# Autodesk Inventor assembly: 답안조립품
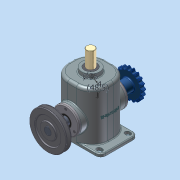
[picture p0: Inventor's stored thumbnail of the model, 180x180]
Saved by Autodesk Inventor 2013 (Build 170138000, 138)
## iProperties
Created: 2014-12
Part Number: 답안조립품
Document SubType Name: Assembly
Designer: WINDOWS7
Author: WINDOWS7
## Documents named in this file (15)
- C:\Users\WINDOWS7\Desktop\341209V1022\답안조립품.iam
- C:\Users\WINDOWS7\Desktop\341209V1022\M4x0.5.ipt
- C:\Users\WINDOWS7\Desktop\341209V1022\V-벨트풀리.ipt
- C:\Users\WINDOWS7\Desktop\341209V1022\멈춤나사 M5x0.5.ipt
- C:\Users\WINDOWS7\Desktop\341209V1022\멈춤링.ipt
- C:\Users\WINDOWS7\Desktop\341209V1022\베어링 6205.ipt
- C:\Users\WINDOWS7\Desktop\341209V1022\본체.ipt
- C:\Users\WINDOWS7\Desktop\341209V1022\부시.ipt
- C:\Users\WINDOWS7\Desktop\341209V1022\스프링-[가변].ipt
- C:\Users\WINDOWS7\Desktop\341209V1022\슬라이드.ipt
- C:\Users\WINDOWS7\Desktop\341209V1022\오일실.ipt
- C:\Users\WINDOWS7\Desktop\341209V1022\체인 스프로킷.ipt
- C:\Users\WINDOWS7\Desktop\341209V1022\커버.ipt
- C:\Users\WINDOWS7\Desktop\341209V1022\키 8x8.ipt
- C:\Users\WINDOWS7\Desktop\341209V1022\편심축.ipt
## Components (8 placed, 3 different names)
1. V-벨트풀리:1 — 플러쉬:1
2. 5-체인 스프로킷:1 — 플러쉬:2
3. M4x0.5:1
4. M4x0.5:3
5. M4x0.5:4
6. M4x0.5:2
7. M4x0.5:5
8. M4x0.5:6
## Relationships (2: Flush 2)
- 플러쉬:1 [Flush]: V-벨트풀리:1
- 플러쉬:2 [Flush]: 5-체인 스프로킷:1
